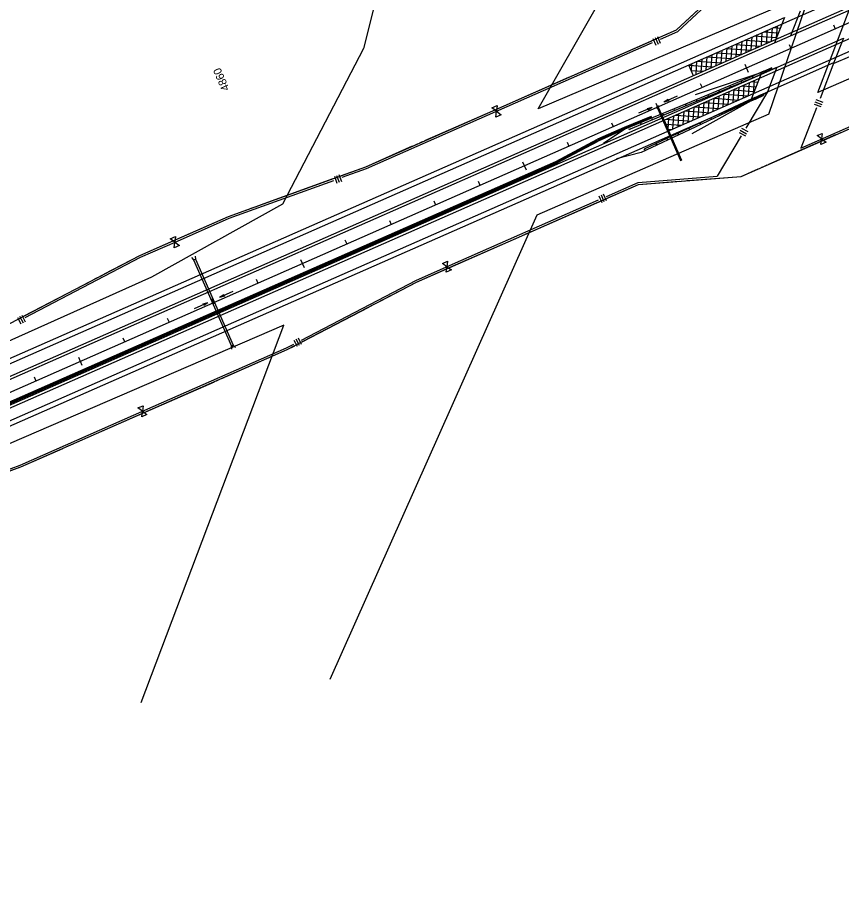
# Model space of a CAD drawing. Extents: x 192699 to 285914, y 194342 to 233219.
# Drawn here: x 231567 to 233265, y 216017 to 217813 of the extents above; entities that cross this region are included whole.
import ezdxf

# ---------------------------------------------------------------- set-up
doc = ezdxf.new("R2010")
doc.units = 0
for name, color, linetype in [('CENT LINE', 7, 'Continuous'), ('CONCRETE', 7, 'Continuous'), ('DRAINAGE', 7, 'Continuous'), ('DRAINAGE ARROWS', 7, 'Continuous'), ('Flood Plain', 7, 'Continuous'), ('GUARDRAIL', 7, 'Continuous'), ('PAVEMENT TRANSITION', 7, 'Continuous'), ('R-W - CofA', 7, 'Continuous'), ('R_Draft', 7, 'Continuous'), ('R_Proposed Guardrail', 7, 'Continuous'), ('R_Water Annot', 7, 'Continuous'), ('ROAD', 7, 'Continuous'), ('SHOULDER', 7, 'Continuous'), ('STATIONING1', 7, 'Continuous'), ('WRSF', 7, 'Continuous')]:
    doc.layers.add(name, color=color, linetype=linetype)

msp = doc.modelspace()

# ---------------------------------------------------------------- linework, layer by layer
at = {"layer": 'CENT LINE'}
msp.add_line((229622.3, 216190.7), (246993.1, 223840), dxfattribs=at)
at = {"layer": 'CONCRETE'}
for p, q in [((232872.7, 217608.9), (232817.3, 217585.8)), ((232874.3, 217605.2), (232872.7, 217608.9)), ((232817.3, 217585.8), (232762.4, 217561.6)), ((232819, 217582.2), (232763.8, 217557.9)), ((232676.2, 217515.8), (232762.4, 217561.6)), ((232677.6, 217512.1), (232763.8, 217557.9)), ((229532.7, 216131.5), (232676.2, 217515.8)), ((229534.3, 216127.9), (232677.6, 217512.1))]:
    msp.add_line(p, q, dxfattribs=at)
at = {"layer": 'DRAINAGE'}
for p, q in [((232886.1, 217625.7), (232933.7, 217517.8)), ((232888, 217626.6), (232935.5, 217518.6)), ((231930.1, 217312.9), (232008.3, 217135.4)), ((231933.8, 217314.5), (232012, 217137))]:
    msp.add_line(p, q, dxfattribs=at)
for points in [[(232885.2, 217625.3), (232888.9, 217627), (232887.3, 217630.6), (232883.6, 217629)], [(231970, 217222.3), (231973.7, 217223.9), (231972.1, 217227.6), (231968.4, 217226)]]:
    msp.add_lwpolyline(points, close=True, dxfattribs=at)
for points in [[(232933.7, 217517.8), (232935.5, 217518.6)], [(231925.9, 217317.6), (231930.1, 217312.9)], [(231930.1, 217312.9), (231933.8, 217314.5)], [(231933.2, 217320.8), (231933.8, 217314.5)], [(232008.3, 217135.4), (232012, 217137)], [(232008.9, 217129.1), (232008.3, 217135.4)], [(232016.2, 217132.3), (232012, 217137)]]:
    msp.add_lwpolyline(points, dxfattribs=at)
at = {"layer": 'DRAINAGE ARROWS'}
for p, q in [((232907.8, 217643.9), (232899.3, 217638.5)), ((232909, 217641.2), (232899.3, 217638.5)), ((232907.9, 217643.7), (232900.8, 217639.2)), ((232908.9, 217641.4), (232900.8, 217639.2)), ((232908, 217643.4), (232902.4, 217639.9)), ((232908.8, 217641.6), (232902.4, 217639.9)), ((232908.1, 217643.2), (232903.9, 217640.5)), ((232908.7, 217641.8), (232903.9, 217640.5)), ((232908.2, 217643), (232905.4, 217641.2)), ((232908.6, 217642.1), (232905.4, 217641.2)), ((232908.3, 217642.7), (232907, 217641.9)), ((232908.5, 217642.3), (232907, 217641.9)), ((232909, 217641.2), (232907.8, 217643.9)), ((232865.4, 217625.3), (232875.2, 217627.9)), ((232866.6, 217622.5), (232865.4, 217625.3)), ((232865.5, 217625.1), (232873.6, 217627.3)), ((232865.6, 217624.8), (232872, 217626.6)), ((232865.7, 217624.6), (232870.5, 217625.9)), ((232865.8, 217624.4), (232869, 217625.2)), ((232865.9, 217624.1), (232867.4, 217624.6)), ((232866.1, 217623.7), (232867.4, 217624.6)), ((232866.2, 217623.5), (232869, 217625.2)), ((232866.3, 217623.2), (232870.5, 217625.9)), ((232866.4, 217623), (232872, 217626.6)), ((232866.5, 217622.8), (232873.6, 217627.3)), ((232866.6, 217622.5), (232875.2, 217627.9)), ((231992.4, 217241), (231983.8, 217235.5)), ((231992.5, 217240.7), (231985.3, 217236.2)), ((231992.6, 217240.5), (231986.9, 217236.9)), ((231992.7, 217240.3), (231988.4, 217237.6)), ((231992.8, 217240), (231990, 217238.3)), ((231992.9, 217239.8), (231991.5, 217238.9)), ((231993.6, 217238.2), (231992.4, 217241)), ((231950, 217222.3), (231959.7, 217225)), ((231951.2, 217219.6), (231950, 217222.3)), ((231950.1, 217222.1), (231958.2, 217224.3)), ((231950.2, 217221.9), (231956.6, 217223.6)), ((231950.3, 217221.7), (231955.1, 217222.9)), ((231950.4, 217221.4), (231953.5, 217222.3)), ((231950.7, 217220.5), (231953.5, 217222.3)), ((231950.9, 217220.3), (231955.1, 217222.9)), ((231951, 217220.1), (231956.6, 217223.6)), ((231951.1, 217219.8), (231958.2, 217224.3)), ((231951.2, 217219.6), (231959.7, 217225)), ((231993.6, 217238.2), (231983.8, 217235.5)), ((231993.5, 217238.4), (231985.3, 217236.2)), ((231993.4, 217238.7), (231986.9, 217236.9)), ((231993.3, 217238.9), (231988.4, 217237.6)), ((231993.2, 217239.1), (231990, 217238.3)), ((231993.1, 217239.4), (231991.5, 217238.9)), ((231950.5, 217221.2), (231952, 217221.6)), ((231950.6, 217220.8), (231952, 217221.6))]:
    msp.add_line(p, q, dxfattribs=at)
at = {"layer": 'Flood Plain'}
for points in [[(236045.8, 218591.8), (235914.4, 218852.7), (235043.1, 218454.5), (233216.3, 217657.8), (233312.5, 217911.7)], [(233115.1, 217613.6), (233200.4, 217863.9), (232639.8, 217624.6), (232762.7, 217839.7), (232858.2, 218126.5), (232878.7, 218351.8)], [(232386, 218172.2), (232280.2, 217748.8), (232113, 217427.9), (231843.4, 217277.7), (231120, 216953.3), (230108.2, 216508.6)], [(233115.1, 217613.6), (232637.1, 217405.1), (232211, 216447.8)], [(231822.2, 216400.5), (232116.4, 217178.5), (229548.4, 216068.7)]]:
    msp.add_lwpolyline(points, dxfattribs=at)
at = {"layer": 'GUARDRAIL'}
for p, q in [((233109.5, 217702.4), (232963.3, 217653.3)), ((233091.5, 217647.7), (232956.8, 217573.2))]:
    msp.add_line(p, q, dxfattribs=at)
at = {"layer": 'PAVEMENT TRANSITION'}
for p, q in [((233100, 217754.9), (233101.9, 217782)), ((233104.9, 217783.3), (233135, 217781.1)), ((233110.3, 217759.4), (233112.3, 217786.5)), ((233120.7, 217764), (233122.6, 217791.1)), ((233124.5, 217791.9), (233138.8, 217790.9)), ((233131.3, 217771.4), (233133, 217795.6)), ((233058.6, 217736.6), (233060.5, 217763.7)), ((233065.8, 217766), (233117, 217762.4)), ((233068.9, 217741.2), (233070.9, 217768.3)), ((233079.3, 217745.8), (233081.2, 217772.8)), ((233085.4, 217774.7), (233131.2, 217771.4)), ((233089.6, 217750.3), (233091.6, 217777.4)), ((233017.2, 217718.4), (233019.1, 217745.5)), ((233026.7, 217748.8), (233077.8, 217745.1)), ((233027.5, 217723), (233029.5, 217750)), ((233037.9, 217727.5), (233039.8, 217754.6)), ((233046.2, 217757.4), (233097.4, 217753.7)), ((233048.2, 217732.1), (233050.2, 217759.2)), ((232975.7, 217700.2), (232977.7, 217727.2)), ((232986.1, 217704.7), (232988, 217731.8)), ((232987.5, 217731.6), (233038.7, 217727.9)), ((232996.4, 217709.3), (232998.4, 217736.4)), ((233006.8, 217713.8), (233008.8, 217740.9)), ((233007.1, 217740.2), (233058.3, 217736.5)), ((232950.1, 217715.1), (232959.7, 217693.1)), ((232950.5, 217714.2), (232999.6, 217710.7)), ((232955.8, 217702), (232957, 217718.1)), ((232965.4, 217695.6), (232967.3, 217722.7)), ((232967.9, 217723), (233019.1, 217719.3)), ((232955, 217703.8), (232980, 217702)), ((232959.6, 217693.5), (232960.4, 217693.4)), ((233060.5, 217671.9), (233088.8, 217669.9)), ((233062.9, 217646.8), (233064.8, 217673.8)), ((233073.2, 217651.3), (233075.2, 217678.4)), ((233080.1, 217680.5), (233092.6, 217679.6)), ((233083.7, 217656.7), (233085.5, 217683)), ((233021.4, 217654.7), (233072.5, 217651)), ((233021.5, 217628.5), (233023.4, 217655.6)), ((233031.8, 217633.1), (233033.8, 217660.2)), ((233040.9, 217663.3), (233085, 217660.1)), ((233042.2, 217637.6), (233044.1, 217664.7)), ((233052.5, 217642.2), (233054.5, 217669.3)), ((232980.1, 217610.3), (232982, 217637.4)), ((232982.2, 217637.5), (233033.4, 217633.8)), ((232990.4, 217614.8), (232992.4, 217641.9)), ((233000.8, 217619.4), (233002.7, 217646.5)), ((233001.8, 217646.1), (233053, 217642.4)), ((233011.1, 217624), (233013.1, 217651)), ((232938.6, 217592), (232940.6, 217619.1)), ((232943.1, 217620.2), (232994.3, 217616.5)), ((232949, 217596.6), (232950.9, 217623.7)), ((232959.3, 217601.2), (232961.3, 217628.2)), ((232962.6, 217628.8), (233013.8, 217625.2)), ((232969.7, 217605.7), (232971.6, 217632.8)), ((232899.7, 217601.1), (232909.4, 217579.2)), ((232903.9, 217603), (232955.1, 217599.3)), ((232907.9, 217582.6), (232909.5, 217605.4)), ((232917.9, 217582.9), (232919.9, 217610)), ((232923.5, 217611.6), (232974.7, 217607.9)), ((232928.3, 217587.5), (232930.2, 217614.6)), ((232903.3, 217593), (232935.6, 217590.7)), ((232907.9, 217582.7), (232916, 217582.1))]:
    msp.add_line(p, q, dxfattribs=at)
at = {"layer": 'R-W - CofA'}
for p, q in [((232876.5, 217769.6), (232882.6, 217755.8)), ((232881.1, 217771.6), (232887.2, 217757.8)), ((232885.7, 217773.6), (232891.8, 217759.8)), ((233210.4, 217639), (233224.5, 217633.7)), ((233212.1, 217643.7), (233226.3, 217638.4)), ((232544.4, 217626.3), (232555.3, 217631.1)), ((232554, 217619.3), (232544.4, 217626.3)), ((232552.7, 217607.5), (232554, 217619.3)), ((232555.3, 217631.1), (232554, 217619.3)), ((232554, 217619.3), (232563.6, 217612.3)), ((233208.6, 217634.2), (233222.8, 217629)), ((232563.6, 217612.3), (232552.7, 217607.5)), ((233058.8, 217584.7), (233072, 217577.4)), ((233053.9, 217575.9), (233067.2, 217568.6)), ((233056.4, 217580.3), (233069.6, 217573)), ((233214.8, 217569.2), (233225.3, 217573.9)), ((233224.1, 217562.4), (233214.8, 217569.2)), ((233225.3, 217573.9), (233224.1, 217562.4)), ((233222.8, 217551), (233224.1, 217562.4)), ((233233.4, 217555.6), (233222.8, 217551)), ((233224.1, 217562.4), (233233.4, 217555.6)), ((232220.2, 217485.5), (232225.3, 217471.3)), ((232224.9, 217487.2), (232230.1, 217473)), ((232229.6, 217488.9), (232234.8, 217474.7)), ((232765.2, 217444.9), (232771.1, 217431.5)), ((232769.7, 217446.9), (232775.6, 217433.5)), ((232774.2, 217448.9), (232780.1, 217435.4)), ((231882.1, 217356.5), (231893, 217361.3)), ((231891.7, 217349.5), (231882.1, 217356.5)), ((231890.4, 217337.7), (231891.7, 217349.5)), ((231893, 217361.3), (231891.7, 217349.5)), ((231891.7, 217349.5), (231901.2, 217342.5)), ((231901.2, 217342.5), (231890.4, 217337.7)), ((232442.8, 217305.8), (232453.3, 217310.5)), ((232452.1, 217299), (232442.8, 217305.8)), ((232450.8, 217287.5), (232452.1, 217299)), ((232453.3, 217310.5), (232452.1, 217299)), ((232452.1, 217299), (232461.3, 217292.2)), ((232461.3, 217292.2), (232450.8, 217287.5)), ((231567.2, 217194.4), (231574.2, 217181)), ((231571.7, 217196.7), (231578.7, 217183.3)), ((231576.1, 217199), (231583.1, 217185.6)), ((232141, 217150.1), (232147.8, 217137.1)), ((232145.3, 217152.3), (232152.1, 217139.3)), ((232136.7, 217147.8), (232143.5, 217134.8)), ((231815.5, 217007.7), (231826, 217012.4)), ((231824.8, 217000.9), (231815.5, 217007.7)), ((231826, 217012.4), (231824.8, 217000.9)), ((231823.5, 216989.5), (231824.8, 217000.9)), ((231834.1, 216994.1), (231823.5, 216989.5)), ((231824.8, 217000.9), (231834.1, 216994.1))]:
    msp.add_line(p, q, dxfattribs=at)
for points in [[(229545.7, 216364.6), (229698, 216431.6), (230271.3, 216618.5), (231552.6, 217182.7), (231819.1, 217321.9), (232002.1, 217402.5), (232284.7, 217505.1), (232925.4, 217787.3), (233080.2, 217931.9), (233354.8, 218052.8), (233566, 218069.4), (234847.3, 218633.6), (234918.7, 218719.6), (235193.2, 218840.5), (235392.4, 218884.5), (236267.2, 219269.8)], [(229698.9, 216016.8), (229851.2, 216083.8), (230376.1, 216380.6), (231291.3, 216783.6), (231573.9, 216886.2), (232123, 217128), (232389.5, 217267.2), (232847.1, 217468.7), (233058.4, 217485.2), (233332.9, 217606.1), (233487.8, 217750.8), (234952.1, 218395.6), (235063.7, 218390.2), (235338.3, 218511.1), (235505.2, 218628.3), (236242.4, 218952.9)], [(232892.5, 217768.4), (232927.6, 217783.8), (233082.5, 217928.5), (233175.2, 217969.4)], [(232890.8, 217772), (232925.4, 217787.3), (233014, 217870.1)], [(232559.4, 217621.7), (232875.9, 217761.1)], [(232728.7, 217700.6), (232874.3, 217764.7)], [(233249.6, 217719.7), (233220.8, 217645.6)], [(232557.8, 217625.4), (232703.4, 217689.5)], [(232708.1, 217691.6), (232713.7, 217694)], [(232718.4, 217696.1), (232724, 217698.6)], [(233181.2, 217543.6), (233330.8, 217609.5), (233399.3, 217673.5)], [(233112.3, 217659.2), (233067.8, 217584.3)], [(232236, 217483.2), (232286.2, 217501.4), (232559.4, 217621.7)], [(232406.8, 217558.9), (232557.8, 217625.4)], [(233213.4, 217626.4), (233181.2, 217543.6)], [(233058.7, 217568.8), (233009.1, 217485.3)], [(233115.6, 217510.4), (233253.5, 217571.2)], [(233258.1, 217573.2), (233263.5, 217575.6)], [(232234.6, 217487), (232284.7, 217505.1), (232381.5, 217547.8)], [(232386.2, 217549.8), (232391.8, 217552.3)], [(232396.5, 217554.4), (232402.1, 217556.8)], [(232957.2, 217477.3), (233058.4, 217485.2), (233093.6, 217500.7)], [(233097.3, 217502.4), (233102.4, 217504.6)], [(233106.6, 217506.5), (233112.2, 217508.9)], [(231897.1, 217351.9), (232003.6, 217398.8), (232219, 217477)], [(232068.1, 217426.5), (232217.6, 217480.8)], [(232780.7, 217443.7), (232846.2, 217472.5), (233009.1, 217485.3)], [(232782.3, 217440.1), (232847.1, 217468.7), (232930.5, 217475.2)], [(232935.4, 217475.6), (232941.4, 217476.1)], [(232946.3, 217476.5), (232952.3, 217476.9)], [(232046.9, 217418.8), (232052.7, 217420.9)], [(232057.5, 217422.6), (232063.3, 217424.7)], [(232457.3, 217301.3), (232764.6, 217436.6)], [(232624.8, 217370.8), (232766.2, 217433.1)], [(231895.5, 217355.6), (232002.1, 217402.5), (232042.1, 217417.1)], [(232614.8, 217366.4), (232620.3, 217368.8)], [(231583.2, 217194.2), (231820.8, 217318.3), (231897.1, 217351.9)], [(231746.8, 217284.2), (231819.1, 217321.9), (231895.5, 217355.6)], [(232458.9, 217297.7), (232600.3, 217360)], [(232604.8, 217362), (232610.3, 217364.4)], [(232152.2, 217147.6), (232387.8, 217270.7), (232457.3, 217301.3)], [(232314.7, 217228.1), (232389.5, 217267.2), (232458.9, 217297.7)], [(231726.9, 217273.8), (231732.3, 217276.6)], [(231736.8, 217279), (231742.3, 217281.8)], [(231581.3, 217197.8), (231722.3, 217271.4)], [(232305, 217223), (232310.3, 217225.8)], [(232154, 217144.2), (232290.9, 217215.7)], [(232295.3, 217218), (232300.6, 217220.7)], [(231830, 217003.2), (232121.3, 217131.5), (232136.6, 217139.5)], [(231997.5, 217072.7), (232123, 217128), (232138.4, 217136)], [(231831.6, 216999.7), (231973, 217061.9)], [(231977.5, 217063.9), (231983, 217066.3)], [(231987.5, 217068.3), (231993, 217070.7)], [(231516.2, 216869.4), (231572.5, 216889.8), (231830, 217003.2)], [(231685, 216935.1), (231831.6, 216999.7)], [(231517.6, 216865.7), (231573.9, 216886.2), (231660.4, 216924.3)], [(231665, 216926.3), (231670.4, 216928.7)], [(231675, 216930.7), (231680.4, 216933.1)]]:
    msp.add_lwpolyline(points, dxfattribs=at)
at = {"layer": 'R_Draft'}
for p, q in [((233086.6, 217647.8), (233103.7, 217655.5)), ((233063.8, 217637.6), (232905.4, 217563.1)), ((233086.6, 217647.8), (233063.8, 217637.6)), ((233088, 217644.6), (233065.2, 217634.4)), ((233088, 217644.6), (233105.2, 217652.3)), ((233065.3, 217634.5), (232952.1, 217581.2)), ((232952.1, 217581.2), (232852.6, 217534.4)), ((232905.4, 217563.1), (232860.1, 217541.8)), ((232852.6, 217534.4), (232801.4, 217521.1)), ((232858.2, 217542), (232860.2, 217541.8)), ((232858.2, 217542), (232859, 217540.2)), ((232859, 217540.2), (232860.2, 217541.8))]:
    msp.add_line(p, q, dxfattribs=at)
for centre in [(233098.3, 217652.2), (233099.8, 217652.9), (233101.2, 217653.5), (233102.6, 217654.1), (233064.1, 217636.9), (233081.2, 217644.6), (233086.9, 217647.1), (233089.8, 217648.4), (233092.6, 217649.7), (233095.5, 217650.9), (233096.9, 217651.6), (233041.4, 217626.3), (232996.2, 217605), (233018.8, 217615.6), (232951, 217583.7), (232973.6, 217594.4), (232905.7, 217562.4), (232928.3, 217573.1), (232883.1, 217551.8)]:
    msp.add_circle(centre, 0.75, dxfattribs=at)
at = {"layer": 'R_Proposed Guardrail'}
for p, q in [((233104.9, 217701.8), (233122, 217709.4)), ((233082.1, 217691.8), (232966.7, 217643.7)), ((233104.9, 217701.8), (233082, 217691.8)), ((233106.3, 217698.6), (233083.4, 217688.6)), ((233106.3, 217698.6), (233123.4, 217706.2)), ((233083.4, 217688.6), (232875.7, 217602)), ((232966.7, 217643.7), (232819, 217582.2)), ((232875.7, 217602), (232829.5, 217582.8)), ((232819, 217582.2), (232774.7, 217553.2)), ((232827.5, 217583), (232829.5, 217582.8)), ((232828.3, 217581.2), (232827.5, 217583)), ((232828.3, 217581.2), (232829.5, 217582.8))]:
    msp.add_line(p, q, dxfattribs=at)
for centre in [(233121.7, 217706.3), (233083.1, 217689.2), (233100.3, 217696.8), (233106, 217699.3), (233108.8, 217700.6), (233111.7, 217701.9), (233114.6, 217703.1), (233116, 217703.7), (233117.4, 217704.4), (233118.9, 217705), (233120.3, 217705.6), (233060, 217679.6), (233013.9, 217660.4), (233036.9, 217670), (232967.7, 217641.2), (232990.8, 217650.8), (232921.5, 217621.9), (232944.6, 217631.6), (232875.4, 217602.7), (232898.5, 217612.3), (232852.3, 217593.1)]:
    msp.add_circle(centre, 0.75, dxfattribs=at)
at = {"layer": 'R_Water Annot'}
for p, q in [((232926.7, 217650.6), (232899.3, 217638.5)), ((232907.8, 217643.9), (232899.3, 217638.5)), ((232909, 217641.2), (232899.3, 217638.5)), ((232907.9, 217643.7), (232900.8, 217639.2)), ((232908.9, 217641.4), (232900.8, 217639.2)), ((232908, 217643.4), (232902.4, 217639.9)), ((232908.8, 217641.6), (232902.4, 217639.9)), ((232908.1, 217643.2), (232903.9, 217640.5)), ((232908.7, 217641.8), (232903.9, 217640.5)), ((232908.2, 217643), (232905.4, 217641.2)), ((232908.6, 217642.1), (232905.4, 217641.2)), ((232908.3, 217642.7), (232907, 217641.9)), ((232908.5, 217642.3), (232907, 217641.9)), ((232909, 217641.2), (232907.8, 217643.9)), ((232847.7, 217615.9), (232875.2, 217627.9)), ((232865.4, 217625.3), (232875.2, 217627.9)), ((232866.6, 217622.5), (232865.4, 217625.3)), ((232865.5, 217625.1), (232873.6, 217627.3)), ((232865.6, 217624.8), (232872, 217626.6)), ((232865.7, 217624.6), (232870.5, 217625.9)), ((232865.8, 217624.4), (232869, 217625.2)), ((232865.9, 217624.1), (232867.4, 217624.6)), ((232866.1, 217623.7), (232867.4, 217624.6)), ((232866.2, 217623.5), (232869, 217625.2)), ((232866.3, 217623.2), (232870.5, 217625.9)), ((232866.4, 217623), (232872, 217626.6)), ((232866.5, 217622.8), (232873.6, 217627.3)), ((232866.6, 217622.5), (232875.2, 217627.9)), ((232011.3, 217247.7), (231983.8, 217235.5)), ((231992.4, 217241), (231983.8, 217235.5)), ((231992.5, 217240.7), (231985.3, 217236.2)), ((231992.6, 217240.5), (231986.9, 217236.9)), ((231992.7, 217240.3), (231988.4, 217237.6)), ((231992.8, 217240), (231990, 217238.3)), ((231992.9, 217239.8), (231991.5, 217238.9)), ((231993.6, 217238.2), (231992.4, 217241)), ((231932.2, 217213), (231959.7, 217225)), ((231950, 217222.3), (231959.7, 217225)), ((231951.2, 217219.6), (231950, 217222.3)), ((231950.1, 217222.1), (231958.2, 217224.3)), ((231950.2, 217221.9), (231956.6, 217223.6)), ((231950.3, 217221.7), (231955.1, 217222.9)), ((231950.4, 217221.4), (231953.5, 217222.3)), ((231950.7, 217220.5), (231953.5, 217222.3)), ((231950.9, 217220.3), (231955.1, 217222.9)), ((231951, 217220.1), (231956.6, 217223.6)), ((231951.1, 217219.8), (231958.2, 217224.3)), ((231951.2, 217219.6), (231959.7, 217225)), ((231993.6, 217238.2), (231983.8, 217235.5)), ((231993.5, 217238.4), (231985.3, 217236.2)), ((231993.4, 217238.7), (231986.9, 217236.9)), ((231993.3, 217238.9), (231988.4, 217237.6)), ((231993.2, 217239.1), (231990, 217238.3)), ((231993.1, 217239.4), (231991.5, 217238.9)), ((231950.5, 217221.2), (231952, 217221.6)), ((231950.6, 217220.8), (231952, 217221.6))]:
    msp.add_line(p, q, dxfattribs=at)
at = {"layer": 'ROAD'}
for p, q in [((229610.2, 216218.1), (246981, 223867.5)), ((229634.4, 216163.2), (247005.2, 223812.6)), ((229644.1, 216141.2), (235816.6, 218859.4)), ((229600.5, 216240.1), (235301.2, 218750.4)), ((233160.3, 217774.9), (233306.2, 217839.1)), ((233123.4, 217706.2), (233269.3, 217770.4)), ((233126.9, 217760.2), (233160.3, 217774.9)), ((233250.2, 217718.3), (233282.2, 217732.4)), ((233098.6, 217695.3), (233132, 217710)), ((233103.7, 217655.5), (233249.6, 217719.7)), ((233078.2, 217642.6), (233112.9, 217657.9))]:
    msp.add_line(p, q, dxfattribs=at)
for points in [[(233180, 217825.6), (233160.3, 217774.9)], [(233147.4, 217812.9), (233126.9, 217760.2)], [(233269.3, 217770.4), (233249.6, 217719.7)], [(233132, 217710), (233112.3, 217659.2)], [(233098.6, 217695.3), (233078.2, 217642.6)]]:
    msp.add_lwpolyline(points, dxfattribs=at)
at = {"layer": 'SHOULDER'}
for p, q in [((229596.5, 216249.2), (233147.4, 217812.9)), ((229612.6, 216212.6), (233126.9, 217760.2)), ((229632, 216168.7), (233098.6, 217695.3)), ((229648.1, 216132.1), (233078.2, 217642.6))]:
    msp.add_line(p, q, dxfattribs=at)
at = {"layer": 'STATIONING1'}
for points in [[(233248.7, 217797.4), (233252.3, 217789.2)], [(233157.2, 217757.1), (233160.8, 217748.9)], [(233065.7, 217716.8), (233072.9, 217700.3)], [(232974.2, 217676.5), (232977.8, 217668.3)], [(232882.6, 217636.2), (232886.3, 217628)], [(232791.1, 217595.9), (232794.7, 217587.7)], [(232699.6, 217555.6), (232703.2, 217547.4)], [(232608.1, 217515.3), (232615.3, 217498.8)], [(232516.6, 217475), (232520.2, 217466.8)], [(232425, 217434.7), (232428.7, 217426.5)], [(232333.5, 217394.4), (232337.1, 217386.2)], [(232242, 217354.1), (232245.6, 217345.9)], [(232150.5, 217313.8), (232157.7, 217297.3)], [(232059, 217273.5), (232062.6, 217265.3)], [(231967.4, 217233.2), (231971.1, 217225)], [(231875.9, 217192.9), (231879.5, 217184.7)], [(231784.4, 217152.6), (231788, 217144.4)], [(231692.9, 217112.3), (231700.1, 217095.8)], [(231601.4, 217072), (231605, 217063.8)]]:
    msp.add_lwpolyline(points, dxfattribs=at)
at = {"layer": 'WRSF'}
for p, q in [((232873.5, 217607.1), (232818.1, 217584)), ((232818.1, 217584), (232763.1, 217559.8)), ((232676.9, 217513.9), (232763.1, 217559.8)), ((229533.5, 216129.7), (232676.9, 217513.9))]:
    msp.add_line(p, q, dxfattribs=at)

# ---------------------------------------------------------------- texts
at = {"layer": 'STATIONING1'}
msp.add_text('4860', height=16.5, rotation=113.7667, dxfattribs=at).set_placement((232004.6, 217665.6))

doc.saveas('drawing.dxf')
